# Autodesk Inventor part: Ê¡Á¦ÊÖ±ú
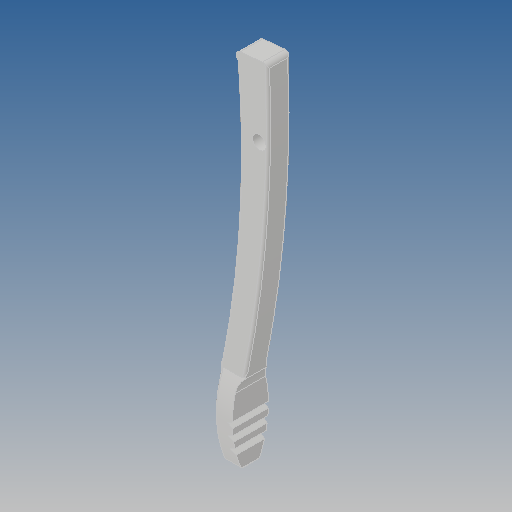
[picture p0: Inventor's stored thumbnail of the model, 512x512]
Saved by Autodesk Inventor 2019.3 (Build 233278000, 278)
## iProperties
Created: 2017-12
Part Number: Ê¡Á¦ÊÖ±ú
Material: Ogólny
Document SubType Name: Modeling
Designer: Admin
Density: 1 g/cm^3
Appearance: Domyślna
Author: Admin
Revision Number: ÈÎºÎ
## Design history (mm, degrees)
feature "Ô²½Ç8"
node "Bryła1"
